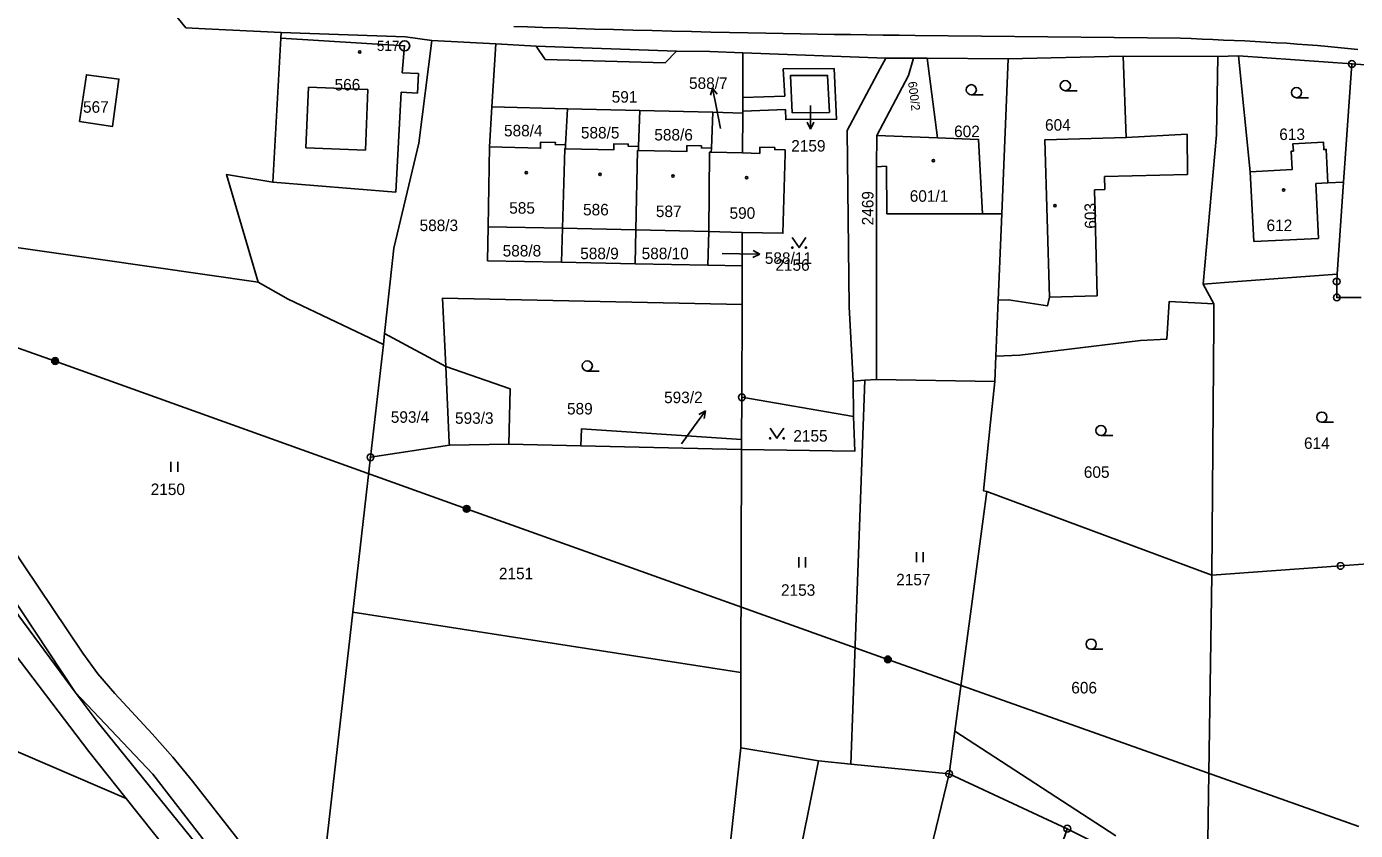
# Model space of a CAD drawing. Extents: x -504988 to -494607, y -1123820 to -1114018.
# Drawn here: x -499475.3 to -499279.1, y -1121578.3 to -1121459.6 of the extents above; entities that cross this region are included whole.
import ezdxf

# ---------------------------------------------------------------- set-up
doc = ezdxf.new("R2010")
doc.units = 0
for name, color, linetype in [('Hranice parcel', 7, 'Continuous'), ('Parcelní čísla', 7, 'Continuous'), ('Pop  PČ popisy', 7, 'Continuous'), ('Poz předměty', 7, 'Continuous'), ('Vnitřní kresba', 7, 'Continuous'), ('Věcná břemena k části', 7, 'Continuous'), ('Značky bodu BP', 7, 'Continuous'), ('Značky budov', 7, 'Continuous'), ('Značky kultur', 7, 'Continuous')]:
    doc.layers.add(name, color=color, linetype=linetype)

msp = doc.modelspace()

# ---------------------------------------------------------------- linework, layer by layer
at = {"layer": 'Hranice parcel'}
for p, q in [((-499415.46, -1121461.66), (-499406.05, -1121462.19)), ((-499406.05, -1121462.19), (-499406.6, -1121471.47)), ((-499369.59, -1121472.4), (-499369.57, -1121463.5)), ((-499369.57, -1121463.5), (-499348.46, -1121464.3)), ((-499344.35, -1121464.3), (-499348.46, -1121464.3)), ((-499342.35, -1121464.3), (-499344.35, -1121464.3)), ((-499330.38, -1121464.41), (-499342.35, -1121464.3)), ((-499340.82, -1121476.06), (-499342.35, -1121464.3)), ((-499331.35, -1121487.3), (-499330.38, -1121464.41)), ((-499313.44, -1121463.99), (-499330.38, -1121464.41)), ((-499299.44, -1121464.06), (-499313.44, -1121463.99)), ((-499296.41, -1121463.94), (-499299.44, -1121464.06)), ((-499296.41, -1121463.94), (-499279.66, -1121465.15)), ((-499280.88, -1121482.58), (-499279.66, -1121465.15)), ((-499275.67, -1121465.44), (-499279.66, -1121465.15)), ((-499406.6, -1121471.47), (-499406.95, -1121477.41)), ((-499395.47, -1121471.75), (-499406.6, -1121471.47)), ((-499395.73, -1121477.08), (-499395.47, -1121471.75)), ((-499384.78, -1121472.02), (-499395.47, -1121471.75)), ((-499384.97, -1121477.33), (-499384.78, -1121472.02)), ((-499373.99, -1121472.29), (-499384.78, -1121472.02)), ((-499374.2, -1121477.58), (-499373.99, -1121472.29)), ((-499373.99, -1121472.29), (-499369.59, -1121472.4)), ((-499369.61, -1121478.29), (-499369.59, -1121472.4)), ((-499349.81, -1121475.73), (-499340.82, -1121476.06)), ((-499406.95, -1121477.41), (-499407.15, -1121489.19)), ((-499395.75, -1121477.68), (-499395.73, -1121477.08)), ((-499384.98, -1121477.93), (-499384.97, -1121477.33)), ((-499374.22, -1121478.18), (-499374.2, -1121477.58)), ((-499369.61, -1121478.29), (-499374.22, -1121478.18)), ((-499367.08, -1121478.35), (-499369.61, -1121478.29)), ((-499281.84, -1121496.17), (-499280.88, -1121482.58)), ((-499331.89, -1121500.04), (-499331.35, -1121487.3)), ((-499407.15, -1121489.19), (-499407.27, -1121494.2)), ((-499407.15, -1121489.19), (-499396.2, -1121489.39)), ((-499396.32, -1121494.41), (-499396.2, -1121489.39)), ((-499396.2, -1121489.39), (-499385.36, -1121489.65)), ((-499385.47, -1121494.66), (-499385.36, -1121489.65)), ((-499385.36, -1121489.65), (-499374.59, -1121489.91)), ((-499374.75, -1121494.88), (-499374.59, -1121489.91)), ((-499374.59, -1121489.91), (-499369.64, -1121490.02)), ((-499369.65, -1121494.97), (-499369.64, -1121490.02)), ((-499407.27, -1121494.2), (-499396.32, -1121494.41)), ((-499396.32, -1121494.41), (-499385.47, -1121494.66)), ((-499385.47, -1121494.66), (-499374.75, -1121494.88)), ((-499374.75, -1121494.88), (-499369.65, -1121494.97)), ((-499369.67, -1121500.66), (-499369.65, -1121494.97)), ((-499300.05, -1121500.56), (-499301.62, -1121497.65)), ((-499281.91, -1121497.27), (-499281.84, -1121496.17)), ((-499369.71, -1121514.38), (-499369.67, -1121500.66)), ((-499332.24, -1121508.31), (-499331.89, -1121500.04)), ((-499422.62, -1121506.58), (-499422.44, -1121504.96)), ((-499413.42, -1121509.81), (-499422.44, -1121504.96)), ((-499424.53, -1121523.24), (-499422.62, -1121506.58)), ((-499332.39, -1121512.03), (-499332.24, -1121508.31)), ((-499353.6, -1121568.54), (-499351.56, -1121511.87)), ((-499351.56, -1121511.87), (-499353.26, -1121512)), ((-499353.26, -1121512), (-499353.22, -1121517.22)), ((-499349.86, -1121511.75), (-499351.56, -1121511.87)), ((-499349.86, -1121511.75), (-499332.39, -1121512.03)), ((-499369.71, -1121514.38), (-499369.74, -1121520.61)), ((-499353.22, -1121517.22), (-499369.71, -1121514.38)), ((-499412.87, -1121521.45), (-499424.53, -1121523.24)), ((-499404.09, -1121521.3), (-499412.87, -1121521.45)), ((-499393.49, -1121521.54), (-499404.09, -1121521.3)), ((-499369.74, -1121522.08), (-499393.49, -1121521.54)), ((-499369.74, -1121520.61), (-499369.74, -1121522.08)), ((-499427.14, -1121546.09), (-499424.53, -1121523.24)), ((-499369.84, -1121555.02), (-499369.74, -1121522.08)), ((-499333.54, -1121528.28), (-499300.35, -1121540.63)), ((-499432.65, -1121594.28), (-499427.14, -1121546.09)), ((-499427.14, -1121546.09), (-499369.84, -1121555.02)), ((-499369.87, -1121566.14), (-499369.84, -1121555.02)), ((-499485.17, -1121563.09), (-499460.6, -1121573.61)), ((-499369.87, -1121566.14), (-499358.39, -1121568.06)), ((-499358.39, -1121568.06), (-499353.6, -1121568.54)), ((-499353.6, -1121568.54), (-499339.12, -1121570)), ((-499363.9, -1121672.76), (-499339.12, -1121570)), ((-499339.12, -1121570), (-499321.67, -1121578.09))]:
    msp.add_line(p, q, dxfattribs=at)
for points in [[(-499437.7, -1121460.51), (-499448.91, -1121459.94), (-499451.77, -1121459.81), (-499453.49, -1121457.69), (-499456.84, -1121455.67), (-499459.58, -1121454.36), (-499462.95, -1121453.35), (-499481.22, -1121448.86)], [(-499437.7, -1121460.51), (-499437.74, -1121461.36), (-499438.95, -1121482.58), (-499445.78, -1121481.46), (-499441.12, -1121497.37)], [(-499415.46, -1121461.66), (-499419.37, -1121461.16), (-499437.7, -1121460.51)], [(-499422.44, -1121504.96), (-499421.32, -1121494.6), (-499421.07, -1121492.34), (-499417.37, -1121476.83), (-499415.46, -1121461.66)], [(-499369.57, -1121463.5), (-499374.44, -1121463.32), (-499379.38, -1121463.26), (-499400.05, -1121462.54), (-499406.05, -1121462.19)], [(-499348.46, -1121464.3), (-499349.27, -1121465.81), (-499354.16, -1121474.97), (-499353.85, -1121501), (-499353.26, -1121512)], [(-499344.35, -1121464.3), (-499345.13, -1121466.86), (-499349.81, -1121475.73)], [(-499313.44, -1121463.99), (-499312.97, -1121476.02), (-499324.97, -1121476.35), (-499324.32, -1121499.57), (-499324.59, -1121500.86), (-499330.35, -1121499.97), (-499331.89, -1121500.04)], [(-499301.62, -1121497.65), (-499299.63, -1121475.61), (-499299.44, -1121464.06)], [(-499280.88, -1121482.58), (-499283.19, -1121482.7), (-499283.45, -1121477.77), (-499283.81, -1121477.79), (-499283.86, -1121476.69), (-499288.36, -1121476.94), (-499288.3, -1121478.02), (-499288.64, -1121478.04), (-499288.5, -1121480.74), (-499294.69, -1121481.06), (-499296.41, -1121463.94)], [(-499467.46, -1121473.65), (-499462.59, -1121474.38), (-499461.66, -1121467.37), (-499466.47, -1121466.75), (-499467.46, -1121473.65)], [(-499356.78, -1121472.32), (-499357.05, -1121466.83), (-499362.54, -1121466.86), (-499362.27, -1121472.35), (-499356.78, -1121472.32)], [(-499349.81, -1121475.73), (-499349.84, -1121480.35), (-499349.85, -1121501.08), (-499349.86, -1121511.75)], [(-499331.35, -1121487.3), (-499334.21, -1121487.29), (-499334.77, -1121476.28), (-499340.82, -1121476.06)], [(-499395.73, -1121477.08), (-499397.25, -1121477.04), (-499397.24, -1121476.74), (-499399.41, -1121476.69), (-499399.43, -1121477.59), (-499406.95, -1121477.41)], [(-499396.2, -1121489.39), (-499395.86, -1121477.68), (-499395.75, -1121477.68)], [(-499384.97, -1121477.33), (-499386.47, -1121477.29), (-499386.47, -1121476.99), (-499388.6, -1121476.94), (-499388.63, -1121477.84), (-499395.75, -1121477.68)], [(-499385.36, -1121489.65), (-499385.11, -1121477.91), (-499384.98, -1121477.93)], [(-499374.2, -1121477.58), (-499375.69, -1121477.55), (-499375.68, -1121477.25), (-499377.82, -1121477.19), (-499377.84, -1121478.1), (-499384.98, -1121477.93)], [(-499374.59, -1121489.91), (-499374.47, -1121478.16), (-499374.22, -1121478.18)], [(-499369.64, -1121490.02), (-499363.64, -1121490.15), (-499363.34, -1121478.44), (-499363.33, -1121477.84), (-499364.86, -1121477.8), (-499364.85, -1121477.5), (-499367.05, -1121477.45), (-499367.08, -1121478.35)], [(-499496.15, -1121489.39), (-499492.38, -1121490.05), (-499464.75, -1121494), (-499441.12, -1121497.37)], [(-499460.6, -1121573.61), (-499466.1, -1121566.69), (-499485.34, -1121541.44), (-499494.5, -1121525.64), (-499510.08, -1121505.52), (-499509.17, -1121503.46), (-499512.68, -1121498.25), (-499516.05, -1121497.37)], [(-499441.12, -1121497.37), (-499436.67, -1121499.9), (-499422.62, -1121506.58)], [(-499301.62, -1121497.65), (-499296.53, -1121497.26), (-499281.84, -1121496.17)], [(-499278.29, -1121499.64), (-499281.88, -1121499.63), (-499281.91, -1121497.27)], [(-499498.18, -1121499.35), (-499482.68, -1121527.98), (-499480.4, -1121531.96), (-499477.94, -1121535.84), (-499467.01, -1121552.15), (-499464.76, -1121555.24), (-499462.28, -1121558.13), (-499456.76, -1121564.07), (-499453.71, -1121567.51), (-499450.82, -1121571.07), (-499432.65, -1121594.28)], [(-499369.67, -1121500.66), (-499413.89, -1121499.72), (-499413.42, -1121509.81)], [(-499505.45, -1121500.48), (-499488.97, -1121526.87), (-499481.08, -1121540.47), (-499468.13, -1121557.9)], [(-499332.24, -1121508.31), (-499328.68, -1121508.17), (-499310.87, -1121505.99), (-499306.98, -1121505.77), (-499306.63, -1121500.21), (-499300.05, -1121500.56)], [(-499300.35, -1121540.63), (-499300.05, -1121503.39), (-499300.05, -1121500.56)], [(-499468.13, -1121557.9), (-499483.92, -1121534.09), (-499499.43, -1121505.45)], [(-499413.42, -1121509.81), (-499403.91, -1121513.15), (-499404.09, -1121521.3)], [(-499413.42, -1121509.81), (-499412.89, -1121521.1), (-499412.87, -1121521.45)], [(-499332.39, -1121512.03), (-499333, -1121518.04), (-499334.04, -1121528.21), (-499333.54, -1121528.28)], [(-499353.22, -1121517.22), (-499353.02, -1121522.32), (-499369.74, -1121522.08)], [(-499393.49, -1121521.54), (-499393.4, -1121519.04), (-499369.74, -1121520.61)], [(-499333.54, -1121528.28), (-499334.09, -1121532.34), (-499338.26, -1121563.68), (-499339.12, -1121570)], [(-499300.35, -1121540.63), (-499281.33, -1121539.28), (-499277.34, -1121538.99), (-499272.2, -1121539.66)], [(-499302.25, -1121591.23), (-499300.99, -1121583.69), (-499300.88, -1121576.43), (-499300.35, -1121540.63)], [(-499375.8, -1121667.41), (-499392.32, -1121652.3), (-499414.56, -1121624.71), (-499433.33, -1121600.19), (-499456.68, -1121570.03), (-499468.13, -1121557.9)], [(-499468.13, -1121557.9), (-499464.88, -1121562.27), (-499447.11, -1121584.2), (-499424.44, -1121621.07), (-499393.57, -1121653.64), (-499382.71, -1121662.67), (-499375.8, -1121667.41)], [(-499389.26, -1121649.45), (-499375.17, -1121614.53), (-499369.87, -1121566.14)], [(-499381.25, -1121656.97), (-499371.85, -1121620.15), (-499365.61, -1121604.16), (-499358.39, -1121568.06)], [(-499282.39, -1121783.87), (-499304.01, -1121752.58), (-499319.36, -1121732.75), (-499332.94, -1121716.66), (-499345.77, -1121703.14), (-499377.06, -1121675.44), (-499391.49, -1121660.89), (-499426.44, -1121623.88), (-499450.61, -1121586.18), (-499460.6, -1121573.61)], [(-499321.67, -1121578.09), (-499356.24, -1121679.91), (-499357.63, -1121683.88)], [(-499321.67, -1121578.09), (-499312.77, -1121582.52), (-499306.33, -1121590.49), (-499302.48, -1121592.57)]]:
    msp.add_lwpolyline(points, dxfattribs=at)
at = {"layer": 'Pop  PČ popisy'}
for p, q in [((-499374.03, -1121468.7), (-499374.33, -1121469.78)), ((-499373.46, -1121471.65), (-499374.03, -1121468.7)), ((-499374.03, -1121468.7), (-499373.35, -1121469.59)), ((-499372.85, -1121474.69), (-499373.46, -1121471.65)), ((-499359.58, -1121471.26), (-499359.58, -1121471.76)), ((-499359.58, -1121471.76), (-499359.58, -1121474.76)), ((-499359.58, -1121474.76), (-499360.08, -1121473.76)), ((-499359.58, -1121474.76), (-499359.08, -1121473.76)), ((-499372.64, -1121493.13), (-499370.07, -1121493.18)), ((-499370.07, -1121493.18), (-499367.07, -1121493.23)), ((-499367.07, -1121493.23), (-499368.08, -1121493.72)), ((-499367.07, -1121493.23), (-499368.06, -1121492.71)), ((-499376.85, -1121518.81), (-499375.09, -1121516.38)), ((-499375.09, -1121516.38), (-499376.08, -1121516.9)), ((-499375.09, -1121516.38), (-499375.27, -1121517.49)), ((-499378.61, -1121521.25), (-499376.85, -1121518.81))]:
    msp.add_line(p, q, dxfattribs=at)
at = {"layer": 'Poz předměty'}
for p, q in [((-499471.08, -1121509.02), (-499543.61, -1121483.42)), ((-499410.34, -1121530.85), (-499471.08, -1121509.02)), ((-499348.15, -1121553.09), (-499410.34, -1121530.85)), ((-499278.62, -1121577.75), (-499348.15, -1121553.09))]:
    msp.add_line(p, q, dxfattribs=at)
for centre, radius in [((-499471.08, -1121509.02), 0.5), ((-499471.08, -1121509.02), 0.4), ((-499471.08, -1121509.02), 0.3), ((-499471.08, -1121509.02), 0.2), ((-499471.08, -1121509.02), 0.1), ((-499410.34, -1121530.85), 0.5), ((-499410.34, -1121530.85), 0.4), ((-499410.34, -1121530.85), 0.3), ((-499410.34, -1121530.85), 0.2), ((-499410.34, -1121530.85), 0.1), ((-499348.15, -1121553.09), 0.5), ((-499348.15, -1121553.09), 0.4), ((-499348.15, -1121553.09), 0.3), ((-499348.15, -1121553.09), 0.2), ((-499348.15, -1121553.09), 0.1)]:
    msp.add_circle(centre, radius, dxfattribs=at)
at = {"layer": 'Vnitřní kresba'}
for p, q in [((-499437.74, -1121461.36), (-499419.49, -1121462.47)), ((-499419.49, -1121462.47), (-499419.83, -1121466.44)), ((-499398.72, -1121464.48), (-499400.05, -1121462.54)), ((-499344.12, -1121460.94), (-499304.95, -1121461.34)), ((-499381.03, -1121464.97), (-499398.72, -1121464.48)), ((-499379.38, -1121463.26), (-499381.03, -1121464.97)), ((-499419.83, -1121466.44), (-499417.43, -1121466.57)), ((-499417.43, -1121466.57), (-499417.59, -1121469.44)), ((-499434.06, -1121477.51), (-499433.69, -1121468.57)), ((-499433.69, -1121468.57), (-499424.9, -1121468.93)), ((-499424.9, -1121468.93), (-499425.27, -1121477.88)), ((-499419.99, -1121469.31), (-499420.78, -1121484.09)), ((-499417.59, -1121469.44), (-499419.99, -1121469.31)), ((-499312.97, -1121476.02), (-499303.96, -1121475.5)), ((-499303.96, -1121475.5), (-499303.92, -1121481.46)), ((-499425.27, -1121477.88), (-499434.06, -1121477.51)), ((-499348.38, -1121480.23), (-499349.84, -1121480.35)), ((-499348.31, -1121487.26), (-499348.38, -1121480.23)), ((-499303.92, -1121481.46), (-499316.2, -1121481.78)), ((-499316.2, -1121481.78), (-499316.15, -1121483.68)), ((-499294.16, -1121491.39), (-499294.69, -1121481.06)), ((-499420.78, -1121484.09), (-499438.95, -1121482.58)), ((-499316.15, -1121483.68), (-499317.68, -1121483.72)), ((-499317.68, -1121483.72), (-499317.24, -1121499.37)), ((-499283.19, -1121482.7), (-499284.99, -1121482.8)), ((-499284.99, -1121482.8), (-499284.57, -1121490.9)), ((-499334.21, -1121487.29), (-499348.31, -1121487.26)), ((-499284.57, -1121490.9), (-499294.16, -1121491.39)), ((-499317.24, -1121499.37), (-499324.32, -1121499.57)), ((-499338.26, -1121563.68), (-499314.53, -1121579.12))]:
    msp.add_line(p, q, dxfattribs=at)
for points in [[(-499403.37, -1121459.61), (-499401.33, -1121459.68), (-499399.11, -1121459.75), (-499396.71, -1121459.83), (-499394.13, -1121459.91), (-499391.45, -1121459.99), (-499388.68, -1121460.06), (-499385.81, -1121460.15), (-499382.93, -1121460.22), (-499380.04, -1121460.3), (-499377.13, -1121460.37), (-499374.3, -1121460.44), (-499371.54, -1121460.5), (-499368.81, -1121460.56), (-499366.18, -1121460.61), (-499363.6, -1121460.66), (-499361.04, -1121460.7), (-499358.55, -1121460.74), (-499356.1, -1121460.78), (-499353.65, -1121460.81), (-499351.25, -1121460.85), (-499348.87, -1121460.88), (-499346.48, -1121460.91), (-499344.12, -1121460.94)], [(-499278.78, -1121463.01), (-499280.27, -1121462.85), (-499281.74, -1121462.71), (-499283.22, -1121462.57), (-499284.73, -1121462.44), (-499286.23, -1121462.32), (-499287.74, -1121462.21), (-499289.28, -1121462.1), (-499290.82, -1121462.01), (-499292.36, -1121461.92), (-499293.93, -1121461.83), (-499295.48, -1121461.75), (-499297.05, -1121461.68), (-499298.63, -1121461.61), (-499300.2, -1121461.54), (-499301.78, -1121461.47), (-499303.37, -1121461.41), (-499304.95, -1121461.34)]]:
    msp.add_lwpolyline(points, dxfattribs=at)
at = {"layer": 'Věcná břemena k části'}
for points in [[(-499369.58, -1121470.12), (-499369.59, -1121472.13), (-499363.29, -1121471.89), (-499363.22, -1121473.36), (-499355.73, -1121473.31), (-499356.1, -1121465.82), (-499363.59, -1121465.87), (-499363.39, -1121469.89)], [(-499356.78, -1121472.32), (-499362.27, -1121472.35), (-499362.54, -1121466.86), (-499357.05, -1121466.83)]]:
    msp.add_lwpolyline(points, close=True, dxfattribs=at)
at = {"layer": 'Značky bodu BP'}
for centre, radius in [((-499419.49, -1121462.47), 0.75), ((-499419.49, -1121462.47), 0.03), ((-499279.66, -1121465.15), 0.5), ((-499279.66, -1121465.15), 0.0303), ((-499281.91, -1121497.27), 0.5), ((-499281.91, -1121497.27), 0.0303), ((-499281.88, -1121499.63), 0.5), ((-499281.88, -1121499.63), 0.0303), ((-499369.71, -1121514.38), 0.5), ((-499369.71, -1121514.38), 0.0303), ((-499424.53, -1121523.24), 0.5), ((-499424.53, -1121523.24), 0.0303), ((-499281.33, -1121539.28), 0.5), ((-499281.33, -1121539.28), 0.0303), ((-499339.12, -1121570), 0.5), ((-499339.12, -1121570), 0.0303), ((-499321.67, -1121578.09), 0.5), ((-499321.67, -1121578.09), 0.0303)]:
    msp.add_circle(centre, radius, dxfattribs=at)
at = {"layer": 'Značky budov'}
for centre in [(-499426.11, -1121463.37), (-499341.44, -1121479.45), (-499401.54, -1121481.21), (-499390.63, -1121481.46), (-499379.88, -1121481.71), (-499369.01, -1121481.96), (-499289.74, -1121483.78), (-499323.49, -1121486.09)]:
    msp.add_circle(centre, 0.175, dxfattribs=at)
at = {"layer": 'Značky kultur'}
for p, q in [((-499335.84, -1121469.7), (-499334.09, -1121469.7)), ((-499321.96, -1121469.1), (-499320.21, -1121469.1)), ((-499287.84, -1121470.13), (-499286.09, -1121470.13)), ((-499392.53, -1121510.5), (-499390.78, -1121510.5)), ((-499284.11, -1121518.06), (-499282.36, -1121518.06)), ((-499316.7, -1121520.02), (-499314.95, -1121520.02)), ((-499453.98, -1121525.39), (-499453.98, -1121523.89)), ((-499452.98, -1121525.39), (-499452.98, -1121523.89)), ((-499343.93, -1121538.73), (-499343.93, -1121537.23)), ((-499342.93, -1121538.73), (-499342.93, -1121537.23)), ((-499361.31, -1121539.51), (-499361.31, -1121538.01)), ((-499360.31, -1121539.51), (-499360.31, -1121538.01)), ((-499318.16, -1121551.58), (-499316.41, -1121551.58))]:
    msp.add_line(p, q, dxfattribs=at)
for points in [[(-499362.26, -1121490.77), (-499361.26, -1121492.27), (-499360.26, -1121490.77)], [(-499365.53, -1121518.92), (-499364.53, -1121520.42), (-499363.53, -1121518.92)]]:
    msp.add_lwpolyline(points, dxfattribs=at)
for centre, radius in [((-499335.84, -1121468.95), 0.75), ((-499321.96, -1121468.35), 0.75), ((-499287.84, -1121469.38), 0.75), ((-499362.26, -1121492.27), 0.1), ((-499360.26, -1121492.27), 0.1), ((-499392.53, -1121509.75), 0.75), ((-499284.11, -1121517.31), 0.75), ((-499316.7, -1121519.27), 0.75), ((-499365.53, -1121520.42), 0.1), ((-499363.53, -1121520.42), 0.1), ((-499318.16, -1121550.83), 0.75)]:
    msp.add_circle(centre, radius, dxfattribs=at)

# ---------------------------------------------------------------- texts
at = {"layer": 'Parcelní čísla'}
for s, p in [('566', (-499429.83, -1121469.06)), ('588/7', (-499377.51, -1121468.83)), ('591', (-499388.92, -1121470.86)), ('567', (-499466.96, -1121472.35)), ('588/4', (-499404.82, -1121475.84)), ('588/5', (-499393.47, -1121476.15)), ('602', (-499338.38, -1121475.95)), ('604', (-499324.96, -1121475)), ('588/6', (-499382.63, -1121476.45)), ('2159', (-499362.42, -1121478.09)), ('613', (-499290.38, -1121476.38)), ('601/1', (-499344.93, -1121485.5)), ('585', (-499404.05, -1121487.26)), ('586', (-499393.15, -1121487.51)), ('587', (-499382.4, -1121487.76)), ('588/3', (-499417.28, -1121489.83)), ('590', (-499371.53, -1121488.01)), ('612', (-499292.26, -1121489.83)), ('588/8', (-499405.02, -1121493.58)), ('588/9', (-499393.57, -1121493.98)), ('588/10', (-499384.5, -1121493.98)), ('588/11', (-499366.32, -1121494.67)), ('2156', (-499364.76, -1121495.69)), ('593/2', (-499381.19, -1121515.24)), ('589', (-499395.52, -1121516.91)), ('593/4', (-499421.53, -1121518.14)), ('593/3', (-499412.05, -1121518.29)), ('2155', (-499362.11, -1121520.92)), ('614', (-499286.73, -1121522)), ('605', (-499319.23, -1121526.27)), ('2150', (-499456.97, -1121528.81)), ('2151', (-499405.57, -1121541.25)), ('2157', (-499346.93, -1121542.15)), ('2153', (-499363.93, -1121543.69)), ('606', (-499321.08, -1121558.11))]:
    msp.add_text(s, height=1.7, dxfattribs=at).set_placement(p)
for s, height, rotation, p in [('600/2', 1.3, 277, (-499345.19, -1121467.8)), ('2469', 1.7, 90, (-499350.28, -1121488.98)), ('603', 1.7, 91, (-499317.38, -1121489.46))]:
    msp.add_text(s, height=height, rotation=rotation, dxfattribs=at).set_placement(p)
at = {"layer": 'Značky bodu BP'}
msp.add_text('517', height=1.5, dxfattribs=at).set_placement((-499423.59, -1121463.22))

doc.saveas('drawing.dxf')
